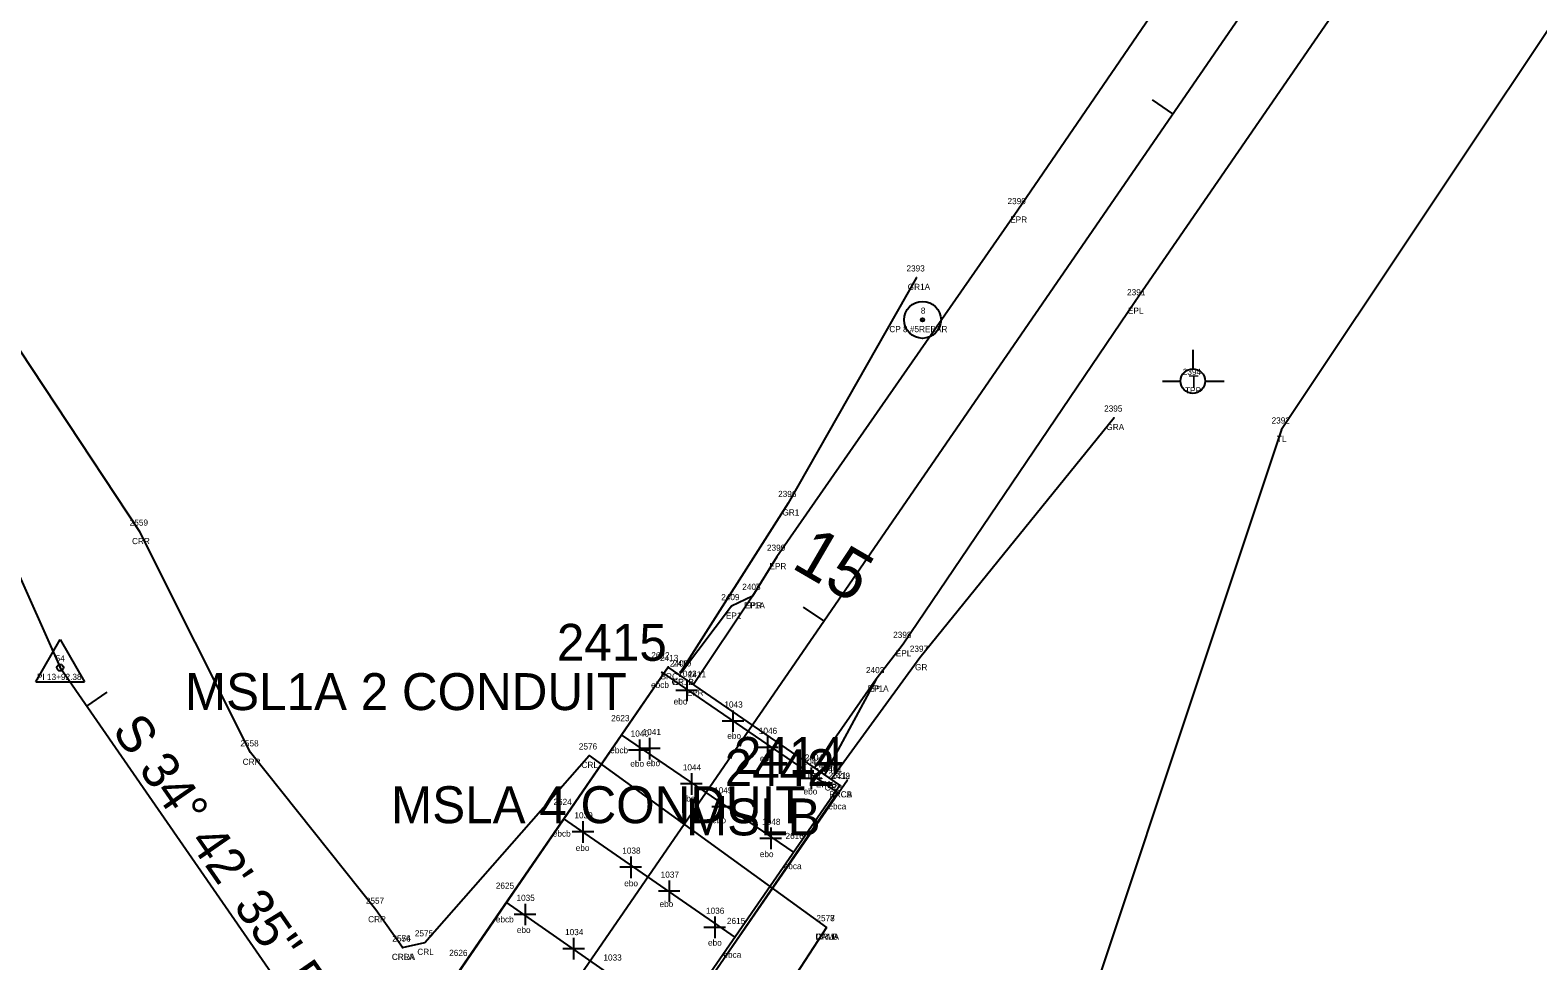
# Model space of a CAD drawing. Extents: x 2266664 to 2272542, y 716533 to 724777.
# Drawn here: x 2271022.9 to 2271267.8, y 722951 to 723102.1 of the extents above; entities that cross this region are included whole.
import ezdxf

# ---------------------------------------------------------------- set-up
doc = ezdxf.new("R2010")
doc.units = 0
for name, color, linetype in [('RD_EX_Bridge', 7, 'Continuous'), ('RD_EX_Bridge_txCode', 7, 'Continuous'), ('RD_EX_Dam', 7, 'Continuous'), ('RD_EX_Dam_txCode', 7, 'Continuous'), ('RD_EX_GuardRail', 7, 'Continuous'), ('RD_EX_GuardRail_txCode', 7, 'Continuous'), ('RD_EX_H2O', 7, 'Continuous'), ('RD_EX_H2O_txCode', 7, 'Continuous'), ('RD_EX_Misc', 7, 'Continuous'), ('RD_EX_Misc_txCode', 7, 'Continuous'), ('RD_EX_Road', 7, 'Continuous'), ('RD_EX_Road_txCode', 7, 'Continuous'), ('RD_EX_UT', 7, 'Continuous'), ('RD_EX_UT_txCode', 7, 'Continuous'), ('RD_EX_VEG', 7, 'Continuous'), ('RD_EX_VEG_txCode', 7, 'Continuous'), ('RD_HC_Cl', 7, 'Continuous'), ('RD_HC_Data', 7, 'Continuous'), ('RD_HC_Data_Tic', 7, 'Continuous'), ('RD_HC_TX_Sta50', 7, 'Continuous'), ('RD_HC_txCode', 7, 'Continuous'), ('RD_SMD_Locator', 7, 'Continuous')]:
    doc.layers.add(name, color=color, linetype=linetype)

msp = doc.modelspace()

# ---------------------------------------------------------------- linework, layer by layer
at = {"layer": 'RD_EX_Bridge'}
msp.add_lwpolyline([(2271154.4, 722979.52), (2271126.52, 722998.67), (2271058.56, 722899.96), (2271086.24, 722880.86), (2271154.4, 722979.52)], dxfattribs=at)
at = {"layer": 'RD_EX_Dam'}
msp.add_lwpolyline([(2271152.21, 722956.41), (2271134.6, 722929.34), (2271126.04, 722916.39), (2271125.72, 722916.12), (2271108.94, 722891.69), (2271108.71, 722891.59), (2271102.6, 722882.8)], dxfattribs=at)
at = {"layer": 'RD_EX_GuardRail'}
for points in [[(2271166.84, 723061.93), (2271146.01, 723025.3), (2271128.48, 722997.77)], [(2271198.94, 723039.17), (2271167.38, 723000.17), (2271153.15, 722980.64)]]:
    msp.add_lwpolyline(points, dxfattribs=at)
at = {"layer": 'RD_EX_H2O'}
for points in [[(2271083.36, 722953.12), (2271079.03, 722959.24), (2271058.65, 722984.8), (2271040.68, 723020.65), (2271013.48, 723061.78), (2270985.21, 723129.14), (2270950.14, 723216.08), (2270917.35, 723303.24), (2270895.25, 723364.78)], [(2271083.36, 722953.12), (2271086.99, 722953.95), (2271113.65, 722984.3), (2271152.21, 722956.41)]]:
    msp.add_lwpolyline(points, dxfattribs=at)
at = {"layer": 'RD_EX_Misc'}
for p, q in [((2271126.58, 722998.7), (2271058.53, 722899.77)), ((2271153.91, 722978.41), (2271125.41, 722997.91)), ((2271131.27, 722994.9), (2271127.77, 722994.9)), ((2271129.52, 722996.65), (2271129.52, 722993.15)), ((2271138.78, 722989.91), (2271135.28, 722989.91)), ((2271137.03, 722991.66), (2271137.03, 722988.16)), ((2271146.95, 722968.56), (2271118.91, 722987.7)), ((2271123.47, 722987.19), (2271123.47, 722983.69)), ((2271142.64, 722987.39), (2271142.64, 722983.89)), ((2271123.59, 722985.19), (2271120.09, 722985.19)), ((2271125.22, 722985.44), (2271121.72, 722985.44)), ((2271121.84, 722986.94), (2271121.84, 722983.44)), ((2271144.39, 722985.64), (2271140.89, 722985.64)), ((2271149.71, 722982.36), (2271149.71, 722978.86)), ((2271155.61, 722980.33), (2271085.82, 722879.3)), ((2271130.27, 722981.45), (2271130.27, 722977.95)), ((2271151.46, 722980.61), (2271147.96, 722980.61)), ((2271086.83, 722880.23), (2271154.05, 722978.35)), ((2271132.02, 722979.7), (2271128.52, 722979.7)), ((2271135.36, 722977.72), (2271135.36, 722974.22)), ((2271137.11, 722975.97), (2271133.61, 722975.97)), ((2271137.42, 722954.76), (2271109.53, 722974.09)), ((2271112.67, 722973.67), (2271112.67, 722970.17)), ((2271143.16, 722972.61), (2271143.16, 722969.11)), ((2271114.42, 722971.92), (2271110.92, 722971.92)), ((2271144.91, 722970.86), (2271141.41, 722970.86)), ((2271120.43, 722967.93), (2271120.43, 722964.43)), ((2271122.18, 722966.18), (2271118.68, 722966.18)), ((2271126.67, 722964.03), (2271126.67, 722960.53)), ((2271128.04, 722941.14), (2271100.17, 722960.49)), ((2271103.26, 722960.26), (2271103.26, 722956.76)), ((2271128.42, 722962.28), (2271124.92, 722962.28)), ((2271105.01, 722958.51), (2271101.51, 722958.51)), ((2271134.06, 722958.17), (2271134.06, 722954.67)), ((2271135.81, 722956.42), (2271132.31, 722956.42)), ((2271112.9, 722952.95), (2271109.4, 722952.95)), ((2271111.15, 722954.7), (2271111.15, 722951.2))]:
    msp.add_line(p, q, dxfattribs=at)
at = {"layer": 'RD_EX_Road'}
msp.add_line((2271160.3, 722996.7), (2271151.91, 722981.18), dxfattribs=at)
for points in [[(2271604.53, 723684.77), (2271550.65, 723606.61), (2271518.33, 723560.15), (2271484.03, 723509.64), (2271377.45, 723356.07), (2271354.74, 723322.34), (2271292.52, 723232.43), (2271237.2, 723151.69), (2271183.29, 723072.86), (2271144.18, 723016.57), (2271140.21, 723010.22), (2271130.75, 722996.02)], [(2271614.21, 723655.35), (2271570.62, 723593.07), (2271532.38, 723537.1), (2271480.53, 723462.42), (2271443.77, 723408.17), (2271407.1, 723356.2), (2271374.69, 723308.79), (2271312.42, 723217.53), (2271256.65, 723136.94), (2271202.38, 723058.06), (2271164.68, 723002.43), (2271160.3, 722996.7), (2271150.37, 722982.5)], [(2271140.21, 723010.22), (2271136.79, 723008.55), (2271128.65, 722997.79)]]:
    msp.add_lwpolyline(points, dxfattribs=at)
at = {"layer": 'RD_EX_UT'}
for p, q in [((2271211.72, 723050.2), (2271211.72, 723047.13)), ((2271206.79, 723045.14), (2271209.72, 723045.14)), ((2271213.72, 723045.14), (2271216.79, 723045.14))]:
    msp.add_line(p, q, dxfattribs=at)
msp.add_circle((2271211.72, 723045.13), 2, dxfattribs=at)
at = {"layer": 'RD_EX_VEG'}
msp.add_lwpolyline([(2271459.81, 723324.47), (2271430.14, 723343.39), (2271397.55, 723294.31), (2271226.14, 723037.24), (2271182.34, 722905.84)], dxfattribs=at)
at = {"layer": 'RD_HC_Cl'}
for p, q in [((2267342.91, 717471.2), (2272360.46, 724762.59)), ((2270970.99, 723125.8), (2271027.76, 722998.59)), ((2271027.76, 722998.59), (2271073.75, 722932.2))]:
    msp.add_line(p, q, dxfattribs=at)
at = {"layer": 'RD_HC_Data'}
for p, q in [((2271023.78, 722996.3), (2271027.76, 723003.18)), ((2271027.76, 723003.18), (2271031.73, 722996.3)), ((2271023.78, 722996.3), (2271031.73, 722996.3))]:
    msp.add_line(p, q, dxfattribs=at)
for centre, radius in [((2271167.82, 723055.07), 3), ((2271167.82, 723055.07), 0.282), ((2271027.76, 722998.59), 0.529)]:
    msp.add_circle(centre, radius, dxfattribs=at)
at = {"layer": 'RD_HC_Data_Tic'}
for p, q in [((2271208.47, 723088.55), (2271205.18, 723090.82)), ((2271151.78, 723006.17), (2271148.49, 723008.44)), ((2271032.09, 722992.33), (2271035.38, 722994.61))]:
    msp.add_line(p, q, dxfattribs=at)
at = {"layer": 'RD_SMD_Locator'}
for centre in [(2271183.29, 723072.86), (2271166.84, 723061.93), (2271202.38, 723058.06), (2271167.82, 723055.07), (2271198.94, 723039.17), (2271226.14, 723037.24), (2271146.01, 723025.3), (2271040.68, 723020.65), (2271144.18, 723016.57), (2271140.21, 723010.22), (2271140.21, 723010.22), (2271136.79, 723008.55), (2271164.68, 723002.43), (2271167.38, 723000.17), (2271027.76, 722998.59), (2271126.52, 722998.67), (2271126.58, 722998.7), (2271128.48, 722997.77), (2271128.65, 722997.79), (2271130.75, 722996.02), (2271160.3, 722996.7), (2271160.3, 722996.7), (2271058.65, 722984.8), (2271113.65, 722984.3), (2271150.37, 722982.5), (2271151.91, 722981.18), (2271153.15, 722980.64), (2271155.61, 722980.33), (2271154.05, 722978.35), (2271154.4, 722979.52), (2271154.4, 722979.52), (2271079.03, 722959.24), (2271152.21, 722956.41), (2271152.21, 722956.41), (2271083.36, 722953.12), (2271083.36, 722953.12), (2271086.99, 722953.95)]:
    msp.add_circle(centre, 0.001, dxfattribs=at)

# ---------------------------------------------------------------- texts
at = {"layer": 'RD_EX_Bridge_txCode'}
for s, p in [('2413', (2271125.18, 722999.67)), ('BRC', (2271125.27, 722996.67)), ('2412', (2271153.06, 722980.52)), ('2419', (2271153.06, 722980.52)), ('BRCA', (2271152.66, 722977.52)), ('BRCB', (2271152.68, 722977.52))]:
    msp.add_text(s, height=1, dxfattribs=at).set_placement(p)
at = {"layer": 'RD_EX_Dam_txCode'}
for s, p in [('2578', (2271150.58, 722957.41)), ('DAMA', (2271150.39, 722954.41))]:
    msp.add_text(s, height=1, dxfattribs=at).set_placement(p)
at = {"layer": 'RD_EX_GuardRail_txCode'}
for s, p in [('2393', (2271165.21, 723062.93)), ('GR1A', (2271165.41, 723059.93)), ('2395', (2271197.31, 723040.17)), ('GRA', (2271197.67, 723037.17)), ('2396', (2271144.36, 723026.3)), ('GR1', (2271145.06, 723023.3)), ('2397', (2271165.75, 723001.17)), ('2406', (2271126.79, 722998.77)), ('GR', (2271166.6, 722998.17)), ('GR1B', (2271127.07, 722995.77)), ('2401', (2271151.77, 722981.64)), ('GRB', (2271151.9, 722978.64))]:
    msp.add_text(s, height=1, dxfattribs=at).set_placement(p)
at = {"layer": 'RD_EX_H2O_txCode'}
for s, p in [('2559', (2271039.05, 723021.65)), ('CRR', (2271039.43, 723018.65)), ('2558', (2271057.02, 722985.8)), ('2576', (2271112, 722985.3)), ('CRR', (2271057.4, 722982.8)), ('CRL', (2271112.43, 722982.3)), ('2557', (2271077.4, 722960.24)), ('CRR', (2271077.78, 722957.24)), ('2577', (2271150.58, 722957.41)), ('2575', (2271085.36, 722954.95)), ('CRLB', (2271150.51, 722954.41)), ('2556', (2271081.7, 722954.12)), ('2574', (2271081.73, 722954.12)), ('CRL', (2271085.76, 722951.95)), ('CRRA', (2271081.62, 722951.12)), ('CRLA', (2271081.64, 722951.12))]:
    msp.add_text(s, height=1, dxfattribs=at).set_placement(p)
at = {"layer": 'RD_EX_Misc_txCode'}
for s, height, p in [('2415', 6, (2271108.43, 722999.7)), ('2622', 1, (2271123.76, 723000.11)), ('MSL1A 2 CONDUIT', 6, (2271048.03, 722991.7)), ('1042', 1, (2271128.14, 722997.1)), ('ebcb', 1, (2271123.73, 722995.3)), ('ebo', 1, (2271127.4, 722992.61)), ('1043', 1, (2271135.64, 722992.11)), ('2623', 1, (2271117.25, 722989.9)), ('1040', 1, (2271120.42, 722987.39)), ('1041', 1, (2271122.36, 722987.64)), ('ebo', 1, (2271136.11, 722987.03)), ('2414', 6, (2271137.19, 722981.33)), ('1046', 1, (2271141.23, 722987.84)), ('ebcb', 1, (2271117.1, 722984.69)), ('2442', 6, (2271135.69, 722979.35)), ('ebo', 1, (2271120.36, 722982.51)), ('ebo', 1, (2271122.96, 722982.59)), ('1044', 1, (2271128.88, 722981.9)), ('ebo', 1, (2271141.39, 722983.35)), ('1047', 1, (2271148.32, 722982.81)), ('2621', 1, (2271152.54, 722980.61)), ('MSLA 4 CONDUIT', 6, (2271081.5, 722973.33)), ('ebo', 1, (2271128.69, 722976.85)), ('MSLB', 6, (2271129.41, 722971.35)), ('1045', 1, (2271133.97, 722978.17)), ('ebo', 1, (2271148.5, 722978)), ('2624', 1, (2271107.87, 722976.29)), ('1039', 1, (2271111.28, 722974.12)), ('ebca', 1, (2271152.53, 722975.58)), ('ebo', 1, (2271133.67, 722973.33)), ('1048', 1, (2271141.77, 722973.06)), ('ebcb', 1, (2271107.77, 722971.15)), ('2616', 1, (2271145.56, 722970.76)), ('ebo', 1, (2271111.49, 722968.82)), ('1038', 1, (2271119.05, 722968.38)), ('ebo', 1, (2271141.39, 722967.82)), ('1037', 1, (2271125.29, 722964.48)), ('ebca', 1, (2271145.27, 722965.87)), ('2625', 1, (2271098.51, 722962.69)), ('ebo', 1, (2271119.37, 722963.08)), ('1035', 1, (2271101.87, 722960.71)), ('ebo', 1, (2271125.1, 722959.71)), ('ebcb', 1, (2271098.52, 722957.22)), ('1036', 1, (2271132.65, 722958.62)), ('2615', 1, (2271136.05, 722956.96)), ('ebo', 1, (2271101.93, 722955.5)), ('1034', 1, (2271109.76, 722955.15)), ('ebo', 1, (2271132.98, 722953.44)), ('2626', 1, (2271090.94, 722951.77)), ('1033', 1, (2271115.99, 722951.02)), ('ebca', 1, (2271135.48, 722951.48))]:
    msp.add_text(s, height=height, dxfattribs=at).set_placement(p)
at = {"layer": 'RD_EX_Road_txCode'}
for s, p in [('2390', (2271181.62, 723073.86)), ('EPR', (2271182.06, 723070.86)), ('2391', (2271201.04, 723059.06)), ('EPL', (2271201.18, 723056.06)), ('2399', (2271142.55, 723017.57)), ('EPR', (2271142.95, 723014.57)), ('2407', (2271138.54, 723011.22)), ('2408', (2271138.54, 723011.22)), ('2409', (2271135.12, 723009.55)), ('EP1A', (2271138.8, 723008.22)), ('EPR', (2271138.98, 723008.22)), ('EP1', (2271135.87, 723006.55)), ('2398', (2271163.05, 723003.43)), ('2410', (2271127.27, 722998.79)), ('EPL', (2271163.47, 723000.43)), ('2411', (2271129.69, 722997.02)), ('2402', (2271158.63, 722997.7)), ('2403', (2271158.63, 722997.7)), ('EP1B', (2271127.26, 722995.79)), ('EPR', (2271129.52, 722994.02)), ('EP1A', (2271158.89, 722994.7)), ('EPL', (2271159.1, 722994.7)), ('2404', (2271148.7, 722983.5)), ('2405', (2271150.24, 722982.18)), ('EPL', (2271149.17, 722980.5)), ('EP1B', (2271150.51, 722979.18))]:
    msp.add_text(s, height=1, dxfattribs=at).set_placement(p)
at = {"layer": 'RD_EX_UT'}
msp.add_text('T', height=2, dxfattribs=at).set_placement((2271211.05, 723044.08))
at = {"layer": 'RD_EX_UT_txCode'}
for s, p in [('2394', (2271210.09, 723046.13)), ('TPP', (2271210.45, 723043.13))]:
    msp.add_text(s, height=1, dxfattribs=at).set_placement(p)
at = {"layer": 'RD_EX_VEG_txCode'}
for s, p in [('2392', (2271224.51, 723038.24)), ('TL', (2271225.37, 723035.24))]:
    msp.add_text(s, height=1, dxfattribs=at).set_placement(p)
at = {"layer": 'RD_HC_Data'}
msp.add_text('S 34%%d 42\' 35" E', height=6, rotation=304.7097, dxfattribs=at).set_placement((2271036.06, 722988.36))
at = {"layer": 'RD_HC_TX_Sta50'}
msp.add_text('15', height=8, rotation=329.7887, dxfattribs=at).set_placement((2271146.32, 723014.92))
at = {"layer": 'RD_HC_txCode'}
for s, p in [('8', (2271167.54, 723056.07)), ('CP 8 #5REBAR', (2271162.42, 723053.07)), ('54', (2271027.02, 722999.59)), ('PI 13+92.38', (2271023.98, 722996.59))]:
    msp.add_text(s, height=1, dxfattribs=at).set_placement(p)

doc.saveas('drawing.dxf')
